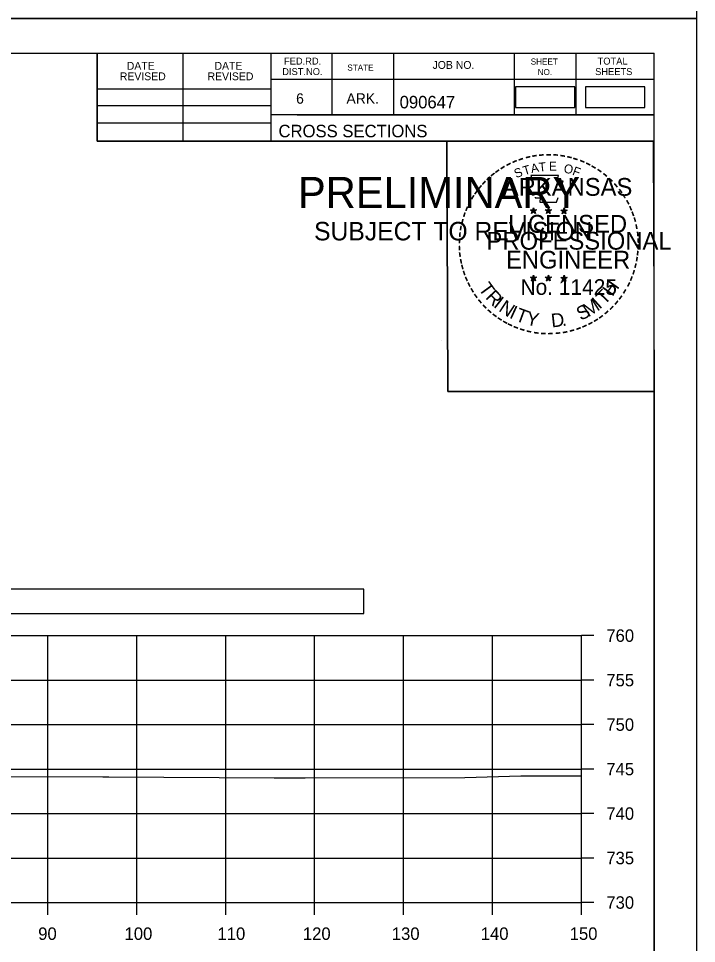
# Model space of a CAD drawing. Extents: x 1202951 to 1376887, y 378065 to 728038.
# Drawn here: x 1376671.4 to 1376747.6, y 379797.2 to 379901.2 of the extents above; entities that cross this region are included whole.
import ezdxf

# ---------------------------------------------------------------- set-up
doc = ezdxf.new("R2010")
doc.units = 0
for name, color, linetype in [('Default', 7, 'Continuous'), ('R_Alt Surface', 7, 'Continuous'), ('R_Axis', 7, 'Continuous'), ('R_Axis Annot', 7, 'Continuous'), ('R_Border', 7, 'Continuous'), ('R_Border PE', 7, 'Continuous'), ('R_Border Prem', 7, 'Continuous'), ('R_Exist Surface', 7, 'Continuous'), ('R_Grid', 7, 'Continuous'), ('R_No Plot', 7, 'Continuous')]:
    doc.layers.add(name, color=color, linetype=linetype)

msp = doc.modelspace()

# ---------------------------------------------------------------- linework, layer by layer
at = {"layer": 'Default'}
msp.add_lwpolyline([(1376735.11, 379891.21), (1376741.79, 379891.21), (1376741.79, 379893.52), (1376735.11, 379893.52)], close=True, dxfattribs=at)
at = {"layer": 'R_Alt Surface'}
for points in [[(1376727.24, 379891.21), (1376733.92, 379891.21), (1376733.92, 379893.52), (1376727.24, 379893.52)], [(1376434.67, 379834.34), (1376710.2, 379834.34), (1376710.2, 379837.05), (1376434.67, 379837.05)]]:
    msp.add_lwpolyline(points, close=True, dxfattribs=at)
at = {"layer": 'R_Axis'}
for p, q in [((1376734.67, 379801.84), (1376734.67, 379831.84)), ((1376736.07, 379831.84), (1376734.67, 379831.84)), ((1376736.07, 379826.84), (1376734.67, 379826.84)), ((1376736.07, 379821.84), (1376734.67, 379821.84)), ((1376736.07, 379816.84), (1376734.67, 379816.84)), ((1376736.07, 379811.84), (1376734.67, 379811.84)), ((1376736.07, 379806.84), (1376734.67, 379806.84)), ((1376434.67, 379801.84), (1376734.67, 379801.84)), ((1376674.67, 379800.44), (1376674.67, 379801.84)), ((1376684.67, 379800.44), (1376684.67, 379801.84)), ((1376694.67, 379800.44), (1376694.67, 379801.84)), ((1376704.67, 379800.44), (1376704.67, 379801.84)), ((1376714.67, 379800.44), (1376714.67, 379801.84)), ((1376724.67, 379800.44), (1376724.67, 379801.84)), ((1376734.67, 379800.44), (1376734.67, 379801.84)), ((1376736.07, 379801.84), (1376734.67, 379801.84))]:
    msp.add_line(p, q, dxfattribs=at)
at = {"layer": 'R_Border'}
for p, q in [((1376426.67, 379897.3), (1376742.85, 379897.3)), ((1376680.21, 379887.42), (1376680.21, 379897.3)), ((1376689.89, 379887.42), (1376689.89, 379897.3)), ((1376699.75, 379897.3), (1376699.75, 379887.42)), ((1376706.59, 379897.3), (1376706.59, 379890.36)), ((1376713.53, 379897.3), (1376713.53, 379890.36)), ((1376727.11, 379897.3), (1376727.11, 379890.36)), ((1376734.05, 379897.3), (1376734.05, 379890.36)), ((1376742.85, 379691.84), (1376742.85, 379897.3)), ((1376742.85, 379894.36), (1376699.75, 379894.36)), ((1376742.85, 379894.38), (1376742.85, 379894.38)), ((1376680.21, 379893.28), (1376699.75, 379893.28)), ((1376680.21, 379891.42), (1376699.75, 379891.42)), ((1376742.85, 379890.36), (1376699.75, 379890.36)), ((1376702.71, 379890.36), (1376742.85, 379890.36)), ((1376680.21, 379889.48), (1376699.75, 379889.48)), ((1376742.85, 379887.42), (1376680.21, 379887.42))]:
    msp.add_line(p, q, dxfattribs=at)
at = {"layer": 'R_Border PE'}
for p, q in [((1376728.94, 379879.68), (1376729.28, 379879.57)), ((1376728.94, 379879.68), (1376729.19, 379879.63)), ((1376728.94, 379879.68), (1376729.17, 379879.56)), ((1376729.07, 379879.27), (1376729.28, 379879.57)), ((1376729.07, 379879.27), (1376729.19, 379879.52)), ((1376729.07, 379879.27), (1376729.28, 379879.49)), ((1376729.28, 379879.93), (1376729.24, 379879.68)), ((1376729.28, 379879.57), (1376729.28, 379879.93)), ((1376729.28, 379879.93), (1376729.33, 379879.68)), ((1376729.63, 379879.68), (1376729.28, 379879.57)), ((1376729.5, 379879.27), (1376729.28, 379879.57)), ((1376729.5, 379879.27), (1376729.28, 379879.49)), ((1376729.63, 379879.68), (1376729.35, 379879.63)), ((1376729.5, 379879.27), (1376729.36, 379879.56)), ((1376729.63, 379879.68), (1376729.43, 379879.58)), ((1376730.61, 379879.68), (1376730.95, 379879.57)), ((1376730.61, 379879.68), (1376730.86, 379879.63)), ((1376730.61, 379879.68), (1376730.84, 379879.56)), ((1376730.74, 379879.27), (1376730.95, 379879.57)), ((1376730.74, 379879.27), (1376730.86, 379879.52)), ((1376730.74, 379879.27), (1376730.95, 379879.49)), ((1376730.95, 379879.93), (1376730.91, 379879.68)), ((1376730.95, 379879.57), (1376730.95, 379879.93)), ((1376730.95, 379879.93), (1376731, 379879.68)), ((1376731.3, 379879.68), (1376730.95, 379879.57)), ((1376731.17, 379879.27), (1376730.95, 379879.57)), ((1376731.17, 379879.27), (1376730.95, 379879.49)), ((1376731.3, 379879.68), (1376731.02, 379879.63)), ((1376731.17, 379879.27), (1376731.03, 379879.56)), ((1376731.3, 379879.68), (1376731.1, 379879.58)), ((1376732.37, 379879.67), (1376732.72, 379879.56)), ((1376732.37, 379879.67), (1376732.62, 379879.62)), ((1376732.37, 379879.67), (1376732.61, 379879.55)), ((1376732.5, 379879.26), (1376732.72, 379879.56)), ((1376732.5, 379879.26), (1376732.63, 379879.5)), ((1376732.5, 379879.26), (1376732.72, 379879.48)), ((1376732.72, 379879.92), (1376732.68, 379879.67)), ((1376732.72, 379879.56), (1376732.72, 379879.92)), ((1376732.72, 379879.92), (1376732.77, 379879.67)), ((1376733.07, 379879.67), (1376732.72, 379879.56)), ((1376732.93, 379879.26), (1376732.72, 379879.56)), ((1376732.93, 379879.26), (1376732.72, 379879.47)), ((1376733.07, 379879.67), (1376732.78, 379879.62)), ((1376732.93, 379879.26), (1376732.79, 379879.55)), ((1376733.07, 379879.67), (1376732.86, 379879.57)), ((1376728.93, 379872.11), (1376729.28, 379872)), ((1376728.93, 379872.11), (1376729.18, 379872.06)), ((1376728.93, 379872.11), (1376729.17, 379871.98)), ((1376729.28, 379872.36), (1376729.24, 379872.11)), ((1376729.28, 379872), (1376729.28, 379872.36)), ((1376729.28, 379872.36), (1376729.33, 379872.11)), ((1376729.63, 379872.11), (1376729.28, 379872)), ((1376729.63, 379872.11), (1376729.34, 379872.06)), ((1376729.63, 379872.11), (1376729.42, 379872)), ((1376730.6, 379872.11), (1376730.95, 379872)), ((1376730.6, 379872.11), (1376730.85, 379872.06)), ((1376730.6, 379872.11), (1376730.84, 379871.98)), ((1376730.95, 379872.36), (1376730.91, 379872.11)), ((1376730.95, 379872), (1376730.95, 379872.36)), ((1376730.95, 379872.36), (1376731, 379872.11)), ((1376731.3, 379872.11), (1376730.95, 379872)), ((1376731.3, 379872.11), (1376731.01, 379872.06)), ((1376731.3, 379872.11), (1376731.09, 379872)), ((1376732.37, 379872.1), (1376732.72, 379871.99)), ((1376732.37, 379872.1), (1376732.62, 379872.05)), ((1376732.37, 379872.1), (1376732.6, 379871.97)), ((1376732.72, 379872.35), (1376732.68, 379872.1)), ((1376732.72, 379871.99), (1376732.72, 379872.35)), ((1376732.72, 379872.35), (1376732.77, 379872.1)), ((1376733.06, 379872.1), (1376732.72, 379871.99)), ((1376733.06, 379872.1), (1376732.78, 379872.05)), ((1376733.06, 379872.1), (1376732.86, 379871.99)), ((1376729.06, 379871.7), (1376729.28, 379872)), ((1376729.06, 379871.7), (1376729.19, 379871.94)), ((1376729.06, 379871.7), (1376729.28, 379871.92)), ((1376729.49, 379871.7), (1376729.28, 379872)), ((1376729.49, 379871.7), (1376729.28, 379871.91)), ((1376729.49, 379871.7), (1376729.36, 379871.99)), ((1376730.73, 379871.7), (1376730.95, 379872)), ((1376730.73, 379871.7), (1376730.86, 379871.94)), ((1376730.73, 379871.7), (1376730.95, 379871.92)), ((1376731.16, 379871.7), (1376730.95, 379872)), ((1376731.16, 379871.7), (1376730.95, 379871.91)), ((1376731.16, 379871.7), (1376731.03, 379871.99)), ((1376732.5, 379871.69), (1376732.72, 379871.99)), ((1376732.5, 379871.69), (1376732.63, 379871.93)), ((1376732.5, 379871.69), (1376732.71, 379871.91)), ((1376732.93, 379871.69), (1376732.71, 379871.9)), ((1376732.93, 379871.69), (1376732.72, 379871.99)), ((1376732.93, 379871.69), (1376732.79, 379871.98))]:
    msp.add_line(p, q, dxfattribs=at)
for points in [[(1376728.98, 379883.56), (1376729.25, 379882.73)], [(1376732.49, 379882.64), (1376732.63, 379882.92), (1376731.94, 379882.9), (1376732.09, 379883.56), (1376728.98, 379883.56)], [(1376729.47, 379881.13), (1376729.47, 379881.05), (1376730.03, 379881.03), (1376729.98, 379880.56), (1376731.85, 379880.56), (1376732.05, 379881.09)], [(1376729.28, 379879.93), (1376729.5, 379879.27), (1376728.94, 379879.68), (1376729.63, 379879.68), (1376729.07, 379879.27), (1376729.28, 379879.93)], [(1376730.95, 379879.93), (1376731.17, 379879.27), (1376730.61, 379879.68), (1376731.3, 379879.68), (1376730.74, 379879.27), (1376730.95, 379879.93)], [(1376732.72, 379879.92), (1376732.93, 379879.26), (1376732.37, 379879.67), (1376733.07, 379879.67), (1376732.5, 379879.26), (1376732.72, 379879.92)], [(1376729.28, 379872.36), (1376729.49, 379871.7), (1376728.93, 379872.11), (1376729.63, 379872.11), (1376729.06, 379871.7), (1376729.28, 379872.36)], [(1376730.95, 379872.36), (1376731.16, 379871.7), (1376730.6, 379872.11), (1376731.3, 379872.11), (1376730.73, 379871.7), (1376730.95, 379872.36)], [(1376732.72, 379872.35), (1376732.93, 379871.69), (1376732.37, 379872.1), (1376733.06, 379872.1), (1376732.5, 379871.69), (1376732.72, 379872.35)]]:
    msp.add_lwpolyline(points, dxfattribs=at)
for centre, radius in [((1376729.28, 379879.57), 0.172), ((1376729.28, 379879.57), 0.145), ((1376729.28, 379879.57), 0.116), ((1376729.28, 379879.57), 0.0991), ((1376729.28, 379879.57), 0.0747), ((1376729.28, 379879.57), 0.0495), ((1376729.28, 379879.57), 0.0296), ((1376730.95, 379879.57), 0.172), ((1376730.95, 379879.57), 0.145), ((1376730.95, 379879.57), 0.116), ((1376730.95, 379879.57), 0.0991), ((1376730.95, 379879.57), 0.0747), ((1376730.95, 379879.57), 0.0495), ((1376730.95, 379879.57), 0.0296), ((1376732.72, 379879.56), 0.172), ((1376732.72, 379879.56), 0.145), ((1376732.72, 379879.56), 0.116), ((1376732.72, 379879.56), 0.0991), ((1376732.72, 379879.56), 0.0747), ((1376732.72, 379879.56), 0.0495), ((1376732.72, 379879.56), 0.0296), ((1376729.28, 379872), 0.172), ((1376729.28, 379872), 0.145), ((1376729.28, 379872), 0.116), ((1376729.28, 379872), 0.0991), ((1376730.95, 379872), 0.172), ((1376730.95, 379872), 0.145), ((1376730.95, 379872), 0.116), ((1376730.95, 379872), 0.0991), ((1376732.72, 379871.99), 0.172), ((1376732.72, 379871.99), 0.145), ((1376732.72, 379871.99), 0.116), ((1376732.72, 379871.99), 0.0991), ((1376729.28, 379872), 0.0747), ((1376729.28, 379872), 0.0495), ((1376729.28, 379872), 0.0296), ((1376730.95, 379872), 0.0747), ((1376730.95, 379872), 0.0495), ((1376730.95, 379872), 0.0296), ((1376732.72, 379871.99), 0.0747), ((1376732.72, 379871.99), 0.0495), ((1376732.72, 379871.99), 0.0296)]:
    msp.add_circle(centre, radius, dxfattribs=at)
at = {"layer": 'R_Exist Surface'}
msp.add_lwpolyline([(1376664.85, 379816), (1376680.87, 379815.96), (1376681.54, 379815.95), (1376700.12, 379815.86), (1376701.55, 379815.84), (1376703.62, 379815.85), (1376721.55, 379815.9), (1376727.85, 379816.07), (1376734.67, 379816.09)], dxfattribs=at)
at = {"layer": 'R_Grid'}
for p, q in [((1376434.67, 379831.84), (1376734.67, 379831.84)), ((1376674.67, 379801.84), (1376674.67, 379831.84)), ((1376684.67, 379801.84), (1376684.67, 379831.84)), ((1376694.67, 379801.84), (1376694.67, 379831.84)), ((1376704.67, 379801.84), (1376704.67, 379831.84)), ((1376714.67, 379801.84), (1376714.67, 379831.84)), ((1376724.67, 379801.84), (1376724.67, 379831.84)), ((1376734.67, 379801.84), (1376734.67, 379831.84)), ((1376434.67, 379826.84), (1376734.67, 379826.84)), ((1376434.67, 379821.84), (1376734.67, 379821.84)), ((1376434.67, 379816.84), (1376734.67, 379816.84)), ((1376434.67, 379811.84), (1376734.67, 379811.84)), ((1376434.67, 379806.84), (1376734.67, 379806.84)), ((1376434.67, 379801.84), (1376734.67, 379801.84))]:
    msp.add_line(p, q, dxfattribs=at)
at = {"layer": 'R_No Plot'}
for p, q in [((1376414.27, 379901.2), (1376747.6, 379901.2)), ((1376718.89, 379864.97), (1376718.89, 379864.97))]:
    msp.add_line(p, q, dxfattribs=at)
for points in [[(1376414.27, 380114.54), (1376747.61, 380114.54), (1376747.61, 379901.2), (1376414.27, 379901.2)], [(1376414.26, 379901.2), (1376747.6, 379901.2), (1376747.6, 379687.86), (1376414.26, 379687.86)], [(1376660.59, 379897.3), (1376680.21, 379897.3), (1376680.21, 379887.42), (1376696.32, 379887.42), (1376719.52, 379887.42), (1376719.64, 379859.27), (1376742.85, 379859.27), (1376742.85, 379691.84), (1376426.67, 379691.84), (1376426.67, 379897.3)], [(1376719.52, 379887.42), (1376742.73, 379887.42), (1376742.85, 379859.27), (1376719.64, 379859.27)]]:
    msp.add_lwpolyline(points, close=True, dxfattribs=at)

# ---------------------------------------------------------------- texts
at = {"layer": 'R_Axis Annot'}
for s, p in [('760', (1376737.47, 379831.14)), ('755', (1376737.47, 379826.14)), ('750', (1376737.47, 379821.14)), ('745', (1376737.47, 379816.14)), ('740', (1376737.47, 379811.14)), ('735', (1376737.47, 379806.14)), ('730', (1376737.47, 379801.14)), ('90', (1376673.59, 379797.64)), ('100', (1376683.3, 379797.64)), ('110', (1376693.75, 379797.64)), ('120', (1376703.35, 379797.64)), ('130', (1376713.35, 379797.64)), ('140', (1376723.35, 379797.64)), ('150', (1376733.35, 379797.64))]:
    msp.add_text(s, height=1.4, dxfattribs=at).set_placement(p)
at = {"layer": 'R_Border'}
for s, height, p in [('DATE', 0.879, (1376683.55, 379895.44)), ('DATE', 0.879, (1376693.41, 379895.44)), ('FED.RD.', 0.782, (1376701.23, 379896.02)), ('STATE', 0.684, (1376708.35, 379895.34)), ('JOB NO.', 0.879, (1376717.93, 379895.54)), ('SHEET', 0.684, (1376728.97, 379896.02)), ('TOTAL', 0.782, (1376736.49, 379896.02)), ('REVISED', 0.879, (1376682.77, 379894.26)), ('REVISED', 0.879, (1376692.63, 379894.26)), ('DIST.NO.', 0.782, (1376701.03, 379894.84)), ('NO.', 0.684, (1376729.75, 379894.84)), ('SHEETS', 0.782, (1376736.21, 379894.84)), ('6', 1.17, (1376702.59, 379891.62)), ('ARK.', 1.172, (1376708.25, 379891.62)), ('090647', 1.4, (1376714.23, 379891.1)), ('CROSS SECTIONS', 1.4, (1376700.61, 379887.85))]:
    msp.add_text(s, height=height, rotation=360, dxfattribs=at).set_placement(p)
at = {"layer": 'R_Border PE'}
for s, height, rotation, p in [('-', 1.6, 13.6301, (1376728.47, 379884.93)), ('-', 1.6, 10.2193, (1376729.15, 379885.09)), ('-', 1.6, 5.8968, (1376729.88, 379885.2)), ('-', 1.6, 0.1862, (1376730.65, 379885.27)), ('-', 1.6, 357.743, (1376731.38, 379885.26)), ('-', 1.6, 352.1617, (1376732.12, 379885.2)), ('-', 1.6, 347.2049, (1376732.84, 379885.09)), ('-', 1.6, 34.0636, (1376725.86, 379883.73)), ('-', 1.6, 28.7918, (1376726.46, 379884.1)), ('-', 1.6, 24.3072, (1376727.09, 379884.42)), ('-', 1.6, 19.1761, (1376727.72, 379884.68)), ('T', 1, 16.4036, (1376728.25, 379883.57)), ('A', 1, 11.2132, (1376729.07, 379883.82)), ('T', 1, 6.0228, (1376729.92, 379883.98)), ('E', 1, 0.8323, (1376731.03, 379884.09)), ('O', 1, 350.4515, (1376732.63, 379883.88)), ('F', 1, 340.0707, (1376733.58, 379883.66)), ('-', 1.6, 342.3362, (1376733.47, 379884.93)), ('-', 1.6, 337.8551, (1376734.21, 379884.71)), ('-', 1.6, 334.1211, (1376734.84, 379884.44)), ('-', 1.6, 329.6409, (1376735.42, 379884.15)), ('-', 1.6, 38.9507, (1376724.81, 379882.96)), ('-', 1.6, 36.2317, (1376725.28, 379883.33)), ('S', 1, 21.594, (1376727.33, 379883.24)), ('-', 1.6, 325.8627, (1376736.06, 379883.79)), ('-', 1.6, 320.5297, (1376736.67, 379883.37)), ('-', 1.6, 50.6142, (1376723.52, 379881.57)), ('-', 1.6, 48.423, (1376723.93, 379882.06)), ('-', 1.6, 42.9622, (1376724.37, 379882.54)), ('ARKANSAS', 2, 360, (1376725.83, 379881.27)), ('-', 1.6, 315.5786, (1376737.27, 379882.88)), ('-', 1.6, 309.8797, (1376737.84, 379882.33)), ('-', 1.6, 54.2325, (1376723.11, 379881.01)), ('-', 1.6, 306.6522, (1376738.37, 379881.73)), ('-', 1.4, 303.6753, (1376738.85, 379881.16)), ('-', 1.6, 62.8713, (1376722.47, 379879.87)), ('-', 1.6, 58.0706, (1376722.78, 379880.48)), ('-', 1.6, 299.6684, (1376739.17, 379880.55)), ('-', 1.6, 72.3945, (1376721.99, 379878.63)), ('-', 1.6, 67.7743, (1376722.21, 379879.26)), ('DWB', 0.01, 360, (1376729.27, 379879.56)), ('DWB', 0.01, 360, (1376730.94, 379879.56)), ('DWB', 0.01, 360, (1376732.71, 379879.55)), ('-', 1.6, 294.6628, (1376739.49, 379879.94)), ('-', 1.6, 290.5728, (1376739.75, 379879.36)), ('-', 1.6, 75.461, (1376721.8, 379877.91)), ('LICENSED', 2, 360, (1376726.43, 379877.12)), ('-', 1.6, 285.1233, (1376739.99, 379878.78)), ('-', 1.6, 81.2013, (1376721.66, 379877.2)), ('-', 1.6, 280.5493, (1376740.19, 379878.04)), ('-', 1.6, 89.0622, (1376721.56, 379875.81)), ('-', 1.6, 85.1863, (1376721.59, 379876.51)), ('PROFESSIONAL', 2, 360, (1376724, 379875.22)), ('-', 1.6, 276.5962, (1376740.35, 379877.27)), ('-', 1.6, 274.3301, (1376740.41, 379876.55)), ('-', 1.6, 94.1959, (1376721.6, 379875.08)), ('-', 1.6, 269.9407, (1376740.44, 379875.92)), ('-', 1.6, 98.9479, (1376721.67, 379874.41)), ('-', 1.6, 101.7149, (1376721.81, 379873.68)), ('ENGINEER', 2, 360, (1376726.19, 379873.09)), ('-', 1.6, 260.9953, (1376740.35, 379874.6)), ('-', 1.6, 263.5172, (1376740.42, 379875.25)), ('-', 1.6, 105.4578, (1376721.97, 379873.09)), ('-', 1.6, 255.7626, (1376740.24, 379873.92)), ('-', 1.6, 109.0874, (1376722.18, 379872.46)), ('-', 1.6, 114.0643, (1376722.44, 379871.86)), ('-', 1.6, 247.8887, (1376739.84, 379872.53)), ('-', 1.6, 252.8681, (1376740.06, 379873.2)), ('-', 1.6, 115.7289, (1376722.74, 379871.24)), ('T', 1.54, 306.0406, (1376723.04, 379870.83)), ('No. 11425', 1.757, 360, (1376727.82, 379870.14)), ('DWB', 0.01, 360, (1376729.27, 379871.99)), ('DWB', 0.01, 360, (1376730.94, 379871.99)), ('DWB', 0.01, 360, (1376732.7, 379871.98)), ('H', 1.54, 54.6088, (1376738.16, 379869.87)), ('-', 1.6, 244.6197, (1376739.58, 379871.9)), ('-', 1.6, 120.4471, (1376723.1, 379870.66)), ('-', 1.6, 125.8934, (1376723.5, 379870.09)), ('R', 1.54, 314.005, (1376723.8, 379869.79)), ('T', 1.54, 46.6444, (1376737.27, 379868.93)), ('-', 1.6, 233.8452, (1376738.78, 379870.49)), ('-', 1.6, 239.0712, (1376739.18, 379871.15)), ('-', 1.6, 130.7181, (1376723.96, 379869.54)), ('-', 1.6, 134.2238, (1376724.48, 379869)), ('I', 1.54, 321.9694, (1376724.7, 379868.85)), ('N', 1.54, 326.5002, (1376725.27, 379868.38)), ('S', 1.54, 26.9312, (1376734.59, 379867.2)), ('M', 1.54, 32.6563, (1376735.43, 379867.6)), ('I', 1.54, 42.1136, (1376736.71, 379868.45)), ('-', 1.6, 231.2538, (1376738.35, 379869.93)), ('-', 1.6, 138.9338, (1376725.01, 379868.53)), ('-', 1.6, 144.6463, (1376725.56, 379868.13)), ('I', 1.54, 335.3603, (1376726.48, 379867.6)), ('T', 1.54, 339.8912, (1376727.14, 379867.27)), ('Y', 1.54, 347.8556, (1376728.36, 379866.82)), ('D', 1.54, 6.3969, (1376731.34, 379866.47)), ('-', 1.6, 221.0851, (1376737.35, 379868.86)), ('-', 1.6, 225.7653, (1376737.87, 379869.36)), ('-', 1.6, 148.0898, (1376726.12, 379867.76)), ('-', 1.6, 151.5704, (1376726.7, 379867.43)), ('-', 1.6, 154.6002, (1376727.22, 379867.18)), ('.', 1.54, 13.7642, (1376732.53, 379866.59)), ('-', 1.6, 207.3568, (1376735.71, 379867.65)), ('-', 1.6, 212.2491, (1376736.27, 379868)), ('-', 1.6, 215.7363, (1376736.8, 379868.38)), ('-', 1.6, 158.5612, (1376727.85, 379866.93)), ('-', 1.6, 162.7983, (1376728.53, 379866.72)), ('-', 1.6, 167.5555, (1376729.25, 379866.55)), ('-', 1.6, 173.1155, (1376730.02, 379866.44)), ('-', 1.6, 176.5183, (1376730.77, 379866.39)), ('-', 1.6, 181.5918, (1376731.51, 379866.41)), ('-', 1.6, 185.8167, (1376732.32, 379866.49)), ('-', 1.6, 191.2858, (1376733.06, 379866.62)), ('-', 1.6, 195.4743, (1376733.79, 379866.82)), ('-', 1.6, 200.7184, (1376734.46, 379867.06)), ('-', 1.6, 204.2516, (1376735.08, 379867.33))]:
    msp.add_text(s, height=height, rotation=rotation, dxfattribs=at).set_placement(p)
at = {"layer": 'R_Border Prem'}
for s, height, p in [('PRELIMINARY', 3.5, (1376702.8, 379879.89)), ('DWB', 0.01, (1376703.55, 379881.74)), ('SUBJECT TO REVISION', 2.0751, (1376704.61, 379876.26))]:
    msp.add_text(s, height=height, rotation=360, dxfattribs=at).set_placement(p)

doc.saveas('drawing.dxf')
